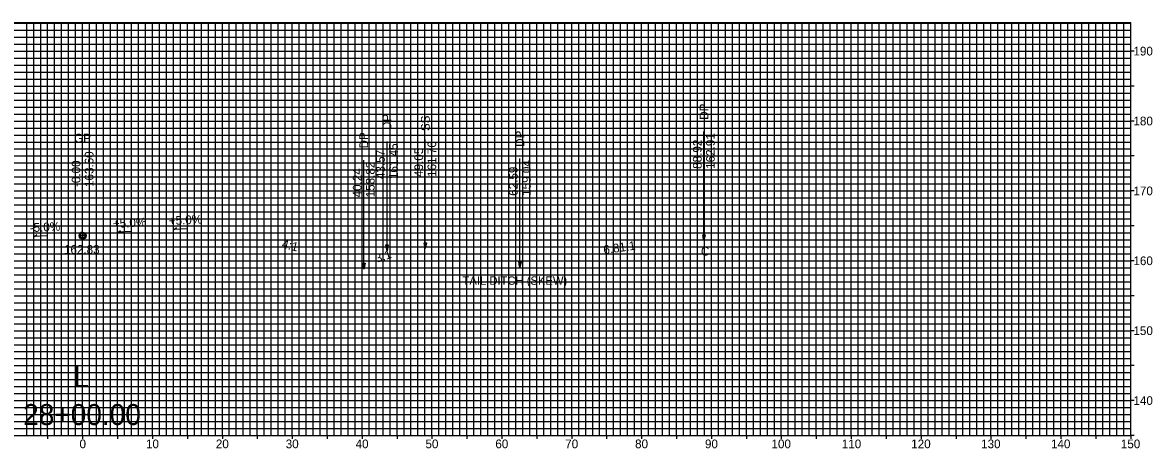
# Model space of a CAD drawing. Extents: x -153 to 153, y 133 to 194.
# Drawn here: x -8.6 to 153.1, y 133.2 to 194.1 of the extents above; entities that cross this region are included whole.
import ezdxf

# ---------------------------------------------------------------- set-up
doc = ezdxf.new("R2010")
doc.units = 0
for name, color, linetype in [('E_NCDOT_XS_Center_Line_Elevation_Label', 7, 'Continuous'), ('P_NCDOT_XS_Label_Grade_Point', 7, 'Continuous'), ('P_NCDOT_XS_Label_Grading_Side_Slope', 7, 'Continuous'), ('P_NCDOT_XS_Label_Slope_Superelevation', 7, 'Continuous'), ('P_NCDOT_XS_Leader_Line', 7, 'Continuous'), ('P_NCDOT_XS_Sheet_Alignment_Station_Label', 7, 'Continuous'), ('P_NCDOT_XS_Sheet_Annotation_Label', 7, 'Continuous'), ('P_NCDOT_XS_Sheet_Grid_Border', 7, 'Continuous'), ('P_NCDOT_XS_Slope_Label', 7, 'Continuous'), ('P_RDY_XS_EOT_Tick_Mark', 7, 'Continuous'), ('Prop XS Grade Point', 7, 'Continuous'), ('Prop XS Label Slope Superelevation', 7, 'Continuous'), ('Scratch_Level_1', 7, 'Continuous'), ('Sheet_Grid_Major', 7, 'Continuous'), ('Sheet_Grid_Middle', 7, 'Continuous'), ('Sheet_Grid_Minor', 7, 'Continuous')]:
    doc.layers.add(name, color=color, linetype=linetype)

msp = doc.modelspace()

# ---------------------------------------------------------------- linework, layer by layer
at = {"layer": 'P_NCDOT_XS_Leader_Line'}
for p, q in [((88.92, 162.91), (88.92, 178.51)), ((0, 163.6), (0, 176.08)), ((62.59, 159.04), (62.59, 174.64)), ((62.59, 159.04), (62.59, 174.64)), ((62.59, 159.04), (62.59, 174.64)), ((40.24, 158.82), (40.24, 174.42)), ((40.24, 158.82), (40.24, 174.42)), ((88.92, 162.91), (88.92, 172.03)), ((62.59, 159.04), (62.59, 168.16)), ((62.59, 159.04), (62.59, 168.16)), ((62.59, 159.04), (62.59, 168.16)), ((40.24, 158.82), (40.24, 167.94)), ((40.24, 158.82), (40.24, 167.94)), ((88.92, 162.91), (88.92, 164.35)), ((40.24, 158.82), (40.24, 160.26)), ((40.24, 158.82), (40.24, 160.26)), ((62.59, 159.04), (62.59, 160.48)), ((62.59, 159.04), (62.59, 160.48)), ((62.59, 159.04), (62.59, 160.48))]:
    msp.add_line(p, q, dxfattribs=at)
for points in [[(0.3, 163.3), (-0.3, 163.3), (-0.3, 163.9), (0.3, 163.9)], [(88.92, 162.91), (88.75, 163.73), (89.1, 163.73)], [(88.92, 162.91), (88.75, 163.73), (89.1, 163.73)], [(88.92, 162.91), (88.83, 163.32), (89.01, 163.32)], [(40.24, 158.82), (40.07, 159.64), (40.42, 159.64)], [(40.24, 158.82), (40.07, 159.64), (40.42, 159.64)], [(40.24, 158.82), (40.07, 159.64), (40.42, 159.64)], [(40.24, 158.82), (40.07, 159.64), (40.42, 159.64)], [(40.24, 158.82), (40.16, 159.23), (40.33, 159.23)], [(40.24, 158.82), (40.16, 159.23), (40.33, 159.23)], [(62.59, 159.04), (62.41, 159.87), (62.77, 159.87)], [(62.59, 159.04), (62.41, 159.87), (62.77, 159.87)], [(62.59, 159.04), (62.41, 159.87), (62.77, 159.87)], [(62.59, 159.04), (62.41, 159.87), (62.77, 159.87)], [(62.59, 159.04), (62.41, 159.87), (62.77, 159.87)], [(62.59, 159.04), (62.41, 159.87), (62.77, 159.87)], [(62.59, 159.04), (62.5, 159.46), (62.68, 159.46)], [(62.59, 159.04), (62.5, 159.46), (62.68, 159.46)], [(62.59, 159.04), (62.5, 159.46), (62.68, 159.46)]]:
    msp.add_lwpolyline(points, close=True, dxfattribs=at)
at = {"layer": 'P_NCDOT_XS_Sheet_Grid_Border'}
for p, q in [((-150, 194.09), (150, 194.09)), ((150, 135), (150, 194.09)), ((-150, 135), (150, 135))]:
    msp.add_line(p, q, dxfattribs=at)
at = {"layer": 'P_RDY_XS_EOT_Tick_Mark'}
msp.add_line((12, 164.2), (12, 164.83), dxfattribs=at)
at = {"layer": 'Prop XS Grade Point'}
for p, q in [((-0.5, 163.6), (0.5, 163.6)), ((0, 164.1), (0, 163.1))]:
    msp.add_line(p, q, dxfattribs=at)
for points in [[(-0.5, 163.6), (0, 163.6), (0, 164.1)], [(0.5, 163.6), (0, 163.6), (0, 163.1)]]:
    msp.add_lwpolyline(points, dxfattribs=at)
msp.add_circle((0, 163.6), 0.5, dxfattribs=at)
for start, end in [(90, 180), (270, 0)]:
    msp.add_arc((0, 163.6), 0.5, start, end, dxfattribs=at)
at = {"layer": 'Prop XS Label Slope Superelevation'}
for p, q in [((-6.9, 163.5), (-6.57, 163.76)), ((-5.1, 163.59), (-6.9, 163.5)), ((5.1, 164.1), (5.43, 164.36)), ((6.9, 164.19), (5.1, 164.1)), ((13.1, 164.5), (13.43, 164.76)), ((14.9, 164.59), (13.1, 164.5))]:
    msp.add_line(p, q, dxfattribs=at)
at = {"layer": 'Scratch_Level_1'}
for p, q in [((43.57, 161.45), (43.57, 177.05)), ((49.05, 161.76), (49.05, 177.36)), ((43.57, 161.45), (43.57, 170.57)), ((49.05, 161.76), (49.05, 170.88)), ((43.57, 161.45), (43.57, 162.89)), ((49.05, 161.76), (49.05, 163.2))]:
    msp.add_line(p, q, dxfattribs=at)
for points in [[(43.57, 161.45), (43.39, 162.27), (43.75, 162.27)], [(43.57, 161.45), (43.39, 162.27), (43.75, 162.27)], [(43.57, 161.45), (43.48, 161.86), (43.66, 161.86)], [(49.05, 161.76), (48.88, 162.58), (49.23, 162.58)], [(49.05, 161.76), (48.88, 162.58), (49.23, 162.58)], [(49.05, 161.76), (48.97, 162.17), (49.14, 162.17)]]:
    msp.add_lwpolyline(points, close=True, dxfattribs=at)
at = {"layer": 'Sheet_Grid_Major'}
for p, q in [((0, 135), (0, 194.09)), ((10, 135), (10, 194.09)), ((20, 135), (20, 194.09)), ((30, 135), (30, 194.09)), ((40, 135), (40, 194.09)), ((50, 135), (50, 194.09)), ((60, 135), (60, 194.09)), ((70, 135), (70, 194.09)), ((80, 135), (80, 194.09)), ((90, 135), (90, 194.09)), ((100, 135), (100, 194.09)), ((110, 135), (110, 194.09)), ((120, 135), (120, 194.09)), ((130, 135), (130, 194.09)), ((140, 135), (140, 194.09)), ((-150, 190), (150, 190)), ((-150, 180), (150, 180)), ((-150, 170), (150, 170)), ((-150, 160), (150, 160)), ((-150, 150), (150, 150)), ((-150, 140), (150, 140))]:
    msp.add_line(p, q, dxfattribs=at)
at = {"layer": 'Sheet_Grid_Middle'}
for p, q in [((-5, 135), (-5, 194.09)), ((0, 135), (0, 194.09)), ((5, 135), (5, 194.09)), ((10, 135), (10, 194.09)), ((15, 135), (15, 194.09)), ((20, 135), (20, 194.09)), ((25, 135), (25, 194.09)), ((30, 135), (30, 194.09)), ((35, 135), (35, 194.09)), ((40, 135), (40, 194.09)), ((45, 135), (45, 194.09)), ((50, 135), (50, 194.09)), ((55, 135), (55, 194.09)), ((60, 135), (60, 194.09)), ((65, 135), (65, 194.09)), ((70, 135), (70, 194.09)), ((75, 135), (75, 194.09)), ((80, 135), (80, 194.09)), ((85, 135), (85, 194.09)), ((90, 135), (90, 194.09)), ((95, 135), (95, 194.09)), ((100, 135), (100, 194.09)), ((105, 135), (105, 194.09)), ((110, 135), (110, 194.09)), ((115, 135), (115, 194.09)), ((120, 135), (120, 194.09)), ((125, 135), (125, 194.09)), ((130, 135), (130, 194.09)), ((135, 135), (135, 194.09)), ((140, 135), (140, 194.09)), ((145, 135), (145, 194.09)), ((-150, 190), (150, 190)), ((150.48, 190), (150, 190)), ((-150, 185), (150, 185)), ((150.48, 185), (150, 185)), ((-150, 180), (150, 180)), ((150.48, 180), (150, 180)), ((-150, 175), (150, 175)), ((150.48, 175), (150, 175)), ((-150, 170), (150, 170)), ((150.48, 170), (150, 170)), ((-150, 165), (150, 165)), ((150.48, 165), (150, 165)), ((-150, 160), (150, 160)), ((150.48, 160), (150, 160)), ((-150, 155), (150, 155)), ((150.48, 155), (150, 155)), ((-150, 150), (150, 150)), ((150.48, 150), (150, 150)), ((-150, 145), (150, 145)), ((150.48, 145), (150, 145)), ((-150, 140), (150, 140)), ((150.48, 140), (150, 140)), ((-5, 135), (-5, 134.52)), ((0, 135), (0, 134.52)), ((5, 135), (5, 134.52)), ((10, 135), (10, 134.52)), ((15, 135), (15, 134.52)), ((20, 135), (20, 134.52)), ((25, 135), (25, 134.52)), ((30, 135), (30, 134.52)), ((35, 135), (35, 134.52)), ((40, 135), (40, 134.52)), ((45, 135), (45, 134.52)), ((50, 135), (50, 134.52)), ((55, 135), (55, 134.52)), ((60, 135), (60, 134.52)), ((65, 135), (65, 134.52)), ((70, 135), (70, 134.52)), ((75, 135), (75, 134.52)), ((80, 135), (80, 134.52)), ((85, 135), (85, 134.52)), ((90, 135), (90, 134.52)), ((95, 135), (95, 134.52)), ((100, 135), (100, 134.52)), ((105, 135), (105, 134.52)), ((110, 135), (110, 134.52)), ((115, 135), (115, 134.52)), ((120, 135), (120, 134.52)), ((125, 135), (125, 134.52)), ((130, 135), (130, 134.52)), ((135, 135), (135, 134.52)), ((140, 135), (140, 134.52)), ((145, 135), (145, 134.52)), ((150, 135), (150, 134.52)), ((150.48, 135), (150, 135))]:
    msp.add_line(p, q, dxfattribs=at)
at = {"layer": 'Sheet_Grid_Minor'}
for p, q in [((-8, 135), (-8, 194.09)), ((-7, 135), (-7, 194.09)), ((-6, 135), (-6, 194.09)), ((-4, 135), (-4, 194.09)), ((-3, 135), (-3, 194.09)), ((-2, 135), (-2, 194.09)), ((-1, 135), (-1, 194.09)), ((1, 135), (1, 194.09)), ((2, 135), (2, 194.09)), ((3, 135), (3, 194.09)), ((4, 135), (4, 194.09)), ((6, 135), (6, 194.09)), ((7, 135), (7, 194.09)), ((8, 135), (8, 194.09)), ((9, 135), (9, 194.09)), ((11, 135), (11, 194.09)), ((12, 135), (12, 194.09)), ((13, 135), (13, 194.09)), ((14, 135), (14, 194.09)), ((16, 135), (16, 194.09)), ((17, 135), (17, 194.09)), ((18, 135), (18, 194.09)), ((19, 135), (19, 194.09)), ((21, 135), (21, 194.09)), ((22, 135), (22, 194.09)), ((23, 135), (23, 194.09)), ((24, 135), (24, 194.09)), ((26, 135), (26, 194.09)), ((27, 135), (27, 194.09)), ((28, 135), (28, 194.09)), ((29, 135), (29, 194.09)), ((31, 135), (31, 194.09)), ((32, 135), (32, 194.09)), ((33, 135), (33, 194.09)), ((34, 135), (34, 194.09)), ((36, 135), (36, 194.09)), ((37, 135), (37, 194.09)), ((38, 135), (38, 194.09)), ((39, 135), (39, 194.09)), ((41, 135), (41, 194.09)), ((42, 135), (42, 194.09)), ((43, 135), (43, 194.09)), ((44, 135), (44, 194.09)), ((46, 135), (46, 194.09)), ((47, 135), (47, 194.09)), ((48, 135), (48, 194.09)), ((49, 135), (49, 194.09)), ((51, 135), (51, 194.09)), ((52, 135), (52, 194.09)), ((53, 135), (53, 194.09)), ((54, 135), (54, 194.09)), ((56, 135), (56, 194.09)), ((57, 135), (57, 194.09)), ((58, 135), (58, 194.09)), ((59, 135), (59, 194.09)), ((61, 135), (61, 194.09)), ((62, 135), (62, 194.09)), ((63, 135), (63, 194.09)), ((64, 135), (64, 194.09)), ((66, 135), (66, 194.09)), ((67, 135), (67, 194.09)), ((68, 135), (68, 194.09)), ((69, 135), (69, 194.09)), ((71, 135), (71, 194.09)), ((72, 135), (72, 194.09)), ((73, 135), (73, 194.09)), ((74, 135), (74, 194.09)), ((76, 135), (76, 194.09)), ((77, 135), (77, 194.09)), ((78, 135), (78, 194.09)), ((79, 135), (79, 194.09)), ((81, 135), (81, 194.09)), ((82, 135), (82, 194.09)), ((83, 135), (83, 194.09)), ((84, 135), (84, 194.09)), ((86, 135), (86, 194.09)), ((87, 135), (87, 194.09)), ((88, 135), (88, 194.09)), ((89, 135), (89, 194.09)), ((91, 135), (91, 194.09)), ((92, 135), (92, 194.09)), ((93, 135), (93, 194.09)), ((94, 135), (94, 194.09)), ((96, 135), (96, 194.09)), ((97, 135), (97, 194.09)), ((98, 135), (98, 194.09)), ((99, 135), (99, 194.09)), ((101, 135), (101, 194.09)), ((102, 135), (102, 194.09)), ((103, 135), (103, 194.09)), ((104, 135), (104, 194.09)), ((106, 135), (106, 194.09)), ((107, 135), (107, 194.09)), ((108, 135), (108, 194.09)), ((109, 135), (109, 194.09)), ((111, 135), (111, 194.09)), ((112, 135), (112, 194.09)), ((113, 135), (113, 194.09)), ((114, 135), (114, 194.09)), ((116, 135), (116, 194.09)), ((117, 135), (117, 194.09)), ((118, 135), (118, 194.09)), ((119, 135), (119, 194.09)), ((121, 135), (121, 194.09)), ((122, 135), (122, 194.09)), ((123, 135), (123, 194.09)), ((124, 135), (124, 194.09)), ((126, 135), (126, 194.09)), ((127, 135), (127, 194.09)), ((128, 135), (128, 194.09)), ((129, 135), (129, 194.09)), ((131, 135), (131, 194.09)), ((132, 135), (132, 194.09)), ((133, 135), (133, 194.09)), ((134, 135), (134, 194.09)), ((136, 135), (136, 194.09)), ((137, 135), (137, 194.09)), ((138, 135), (138, 194.09)), ((139, 135), (139, 194.09)), ((141, 135), (141, 194.09)), ((142, 135), (142, 194.09)), ((143, 135), (143, 194.09)), ((144, 135), (144, 194.09)), ((146, 135), (146, 194.09)), ((147, 135), (147, 194.09)), ((148, 135), (148, 194.09)), ((149, 135), (149, 194.09)), ((-150, 194), (150, 194)), ((-150, 193), (150, 193)), ((-150, 192), (150, 192)), ((-150, 191), (150, 191)), ((-150, 189), (150, 189)), ((-150, 188), (150, 188)), ((-150, 187), (150, 187)), ((-150, 186), (150, 186)), ((-150, 184), (150, 184)), ((-150, 183), (150, 183)), ((-150, 182), (150, 182)), ((-150, 181), (150, 181)), ((-150, 179), (150, 179)), ((-150, 178), (150, 178)), ((-150, 177), (150, 177)), ((-150, 176), (150, 176)), ((-150, 174), (150, 174)), ((-150, 173), (150, 173)), ((-150, 172), (150, 172)), ((-150, 171), (150, 171)), ((-150, 169), (150, 169)), ((-150, 168), (150, 168)), ((-150, 167), (150, 167)), ((-150, 166), (150, 166)), ((-150, 164), (150, 164)), ((-150, 163), (150, 163)), ((-150, 162), (150, 162)), ((-150, 161), (150, 161)), ((-150, 159), (150, 159)), ((-150, 158), (150, 158)), ((-150, 157), (150, 157)), ((-150, 156), (150, 156)), ((-150, 154), (150, 154)), ((-150, 153), (150, 153)), ((-150, 152), (150, 152)), ((-150, 151), (150, 151)), ((-150, 149), (150, 149)), ((-150, 148), (150, 148)), ((-150, 147), (150, 147)), ((-150, 146), (150, 146)), ((-150, 144), (150, 144)), ((-150, 143), (150, 143)), ((-150, 142), (150, 142)), ((-150, 141), (150, 141)), ((-150, 139), (150, 139)), ((-150, 138), (150, 138)), ((-150, 137), (150, 137)), ((-150, 136), (150, 136))]:
    msp.add_line(p, q, dxfattribs=at)

# ---------------------------------------------------------------- texts
at = {"layer": 'E_NCDOT_XS_Center_Line_Elevation_Label'}
msp.add_text('162.83', height=1.248, dxfattribs=at).set_placement((-2.67, 161))
at = {"layer": 'P_NCDOT_XS_Label_Grade_Point'}
msp.add_text('GP', height=1.248, dxfattribs=at).set_placement((-1.22, 176.93))
for s, p in [('162.91', (90.47, 173.16)), ('88.92', (88.6, 173.16)), ('163.60', (1.56, 170.56)), ('-0.00', (-0.31, 170.56)), ('40.24', (39.92, 169.08)), ('158.82', (41.8, 169.08)), ('62.59', (62.27, 169.3)), ('159.04', (64.14, 169.3))]:
    msp.add_text(s, height=1.248, rotation=90, dxfattribs=at).set_placement(p)
at = {"layer": 'P_NCDOT_XS_Label_Grading_Side_Slope'}
for p in [(89.55, 179.71), (40.87, 175.62), (40.87, 175.62), (63.21, 175.84), (63.21, 175.84), (63.21, 175.84)]:
    msp.add_text(' DP', height=1.248, rotation=90, dxfattribs=at).set_placement(p)
msp.add_text('C', height=1.25, dxfattribs=at).set_placement((88.49, 160.74))
at = {"layer": 'P_NCDOT_XS_Label_Slope_Superelevation'}
for s, p in [('-5.0%', (-7.54, 164.1)), ('+5.0%', (4.36, 164.7))]:
    msp.add_text(s, height=1.248, rotation=2.8624, dxfattribs=at).set_placement(p)
at = {"layer": 'P_NCDOT_XS_Sheet_Alignment_Station_Label'}
for s, height, p in [('TAIL DITCH (SKEW)', 1.2, (54.38, 156.57)), ('L', 3, (-1.32, 141.9)), ('28+00.00', 3, (-8.5, 136.5))]:
    msp.add_text(s, height=height, dxfattribs=at).set_placement(p)
at = {"layer": 'P_NCDOT_XS_Sheet_Annotation_Label'}
for s, height, p in [('190', 1.248, (150.39, 189.38)), ('180', 1.248, (150.39, 179.38)), ('170', 1.248, (150.39, 169.38)), ('160', 1.248, (150.39, 159.38)), ('150', 1.248, (150.39, 149.38)), ('140', 1.248, (150.39, 139.38)), ('0', 1.25, (-0.44, 133.18)), ('10', 1.248, (9.07, 133.18)), ('20', 1.248, (19.07, 133.18)), ('30', 1.248, (29.07, 133.18)), ('40', 1.248, (39.07, 133.18)), ('50', 1.248, (49.07, 133.18)), ('60', 1.248, (59.07, 133.18)), ('70', 1.248, (69.07, 133.18)), ('80', 1.248, (79.07, 133.18)), ('90', 1.248, (89.07, 133.18)), ('100', 1.248, (98.59, 133.18)), ('110', 1.248, (108.65, 133.18)), ('120', 1.248, (118.59, 133.18)), ('130', 1.248, (128.59, 133.18)), ('140', 1.248, (138.59, 133.18)), ('150', 1.248, (148.59, 133.18))]:
    msp.add_text(s, height=height, dxfattribs=at).set_placement(p)
at = {"layer": 'P_NCDOT_XS_Slope_Label'}
for s, rotation, p in [('+5.0%', 2.8624, (12.36, 165.1)), ('+5.0%', 2.8624, (12.36, 165.1)), ('4:1', 345.9638, (28.43, 161.89)), ('6.81:1', 8.3504, (74.62, 160.94)), ('3:1', 18.4332, (42.12, 159.7))]:
    msp.add_text(s, height=1.248, rotation=rotation, dxfattribs=at).set_placement(p)
at = {"layer": 'Scratch_Level_1'}
for s, p in [(' DP', (44.19, 178.25)), ('SS', (49.68, 178.56)), ('161.45', (45.12, 171.7)), ('161.76', (50.61, 172.01)), ('43.57', (43.25, 171.7)), ('49.05', (48.73, 172.01))]:
    msp.add_text(s, height=1.248, rotation=90, dxfattribs=at).set_placement(p)

doc.saveas('drawing.dxf')
